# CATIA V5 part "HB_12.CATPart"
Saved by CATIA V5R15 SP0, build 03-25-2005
Part number: HB_12
Bounding box of the stored display mesh (mm): x -79 to 0, y 0 to 948, z 0 to 113.2
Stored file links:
  E:\#01 CATIA Lecture Materials\#06 DMU\#11 DMU Page01 KIN EX11\HB_12.CATPart
  E:\공학과제\HB-16.CATPart
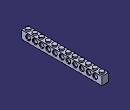
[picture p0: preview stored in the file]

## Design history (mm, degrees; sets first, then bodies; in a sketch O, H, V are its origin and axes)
Body1 (main body)
  Sketch1 on xy-plane, origin (0, 0, 0), H (1, 0, 0), V (0, 1, 0)
    circle A1 centre (-39.5, 39.5) radius 24.5
    point P1 (-39.5, 39.5)
    reference projected line E1 (0, 0) -> (0, 1264)
    reference projected line E2 (-79, 0) -> (-79, 1264)
    reference projected line E3 (-79, 0) -> (0, 0)
    radius A1 = 24.5
    distance P1 E3 = 39.5
    equidistance: E1 E2 P1
  Pad1: profile Sketch1, direction (0, 0, 1), length 113.2
  RectPattern1: of the body so far, direction 1 instances 12, spacing 79, along yz-plane
  Sketch2 on zx-plane, origin (0, 0, 0), H (-1, 0, 0), V (0, 0, 1)
    point P1 (0, 96)
    line L1 (0, 96) -> (79, 96)
    line L2 (79, 96) -> (79, 0)
    line L3 (79, 0) -> (0, 0)
    line L4 (0, 0) -> (0, 96)
    point P3 (79, 0)
    distance L2 L4 = 79
    length L2 = 96
    coincidence: P1 V, P3 H
    horizontal: L1 H, L3 H
    vertical: L2 V, L4 V
  Pad2: profile Sketch2, direction (0, 1, 0), length 948 {= RectPattern1.Nb1 * (79*1mm)}
  Plane1: type Offset, RefPlane zx-plane, Offset 79
  Sketch3 on Plane1, origin (0, 79, 0), H (-1, 0, 0), V (0, 0, 1)
    axis line L1 (95.3003, 56) -> (-23.8651, 56)
    reference projected line E1 (79, 96) -> (0, 96) from edge [start face of Pad2 | face of Pad2 from Sketch2.L1]
    point P3 (79, 56)
    line L2 (79, 56) -> (79, 85.25)
    line L3 (79, 85.25) -> (69, 85.25)
    line L4 (69, 85.25) -> (69, 80.25)
    line L5 (69, 80.25) -> (10, 80.25)
    line L6 (10, 80.25) -> (10, 85.25)
    point P8 (10, 85.25)
    line L7 (10, 85.25) -> (0, 85.25)
    point P9 (0, 85.25)
    line L8 (0, 85.25) -> (0, 56)
    point P10 (0, 56)
    reference projected line E2 (79, 0) -> (79, 96) from edge [start face of Pad2 | face of Pad2 from Sketch2.L2]
    distance L1 E1 = 40
    distance L8 L6 = 10
    distance L4 L2 = 10
    distance L5 L1 = 24.25
    distance L7 L1 = 29.25
    horizontal: L1 H, L3 H, L5 H, L7 H
    coincidence: P3 L1, P8 L3, P9 V, P10 L1, L2 E2
    vertical: L2 V, L4 V, L6 V, L8 V
  Groove1: profile Sketch3, axis Sketch3.L1, angle 360
  RectPattern2: of Groove1, direction 1 instances 11 {= RectPattern1.Nb1 - 1}, spacing 79, along edge [face of Pad2 from Sketch2.L4 | face of Pad2 from Sketch2.L1]
  Shell1: ExtOffset 0, Face face of Pad2, IntOffset 10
